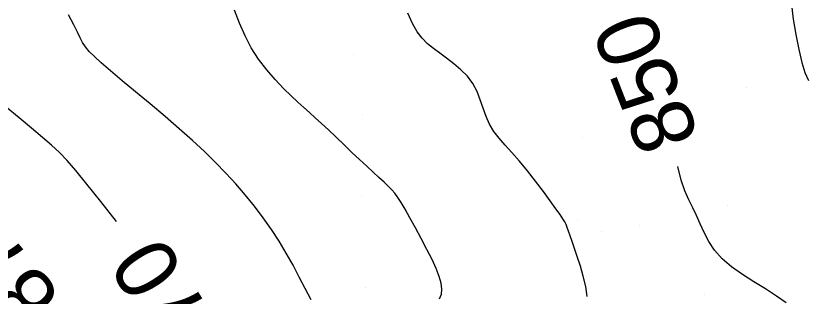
# Model space of a CAD drawing. Extents: x 400243 to 403697, y 4403637 to 4408083.
# Drawn here: x 402859.8 to 402954.4, y 4406058.5 to 4406092.2 of the extents above; entities that cross this region are included whole.
import ezdxf

# ---------------------------------------------------------------- set-up
doc = ezdxf.new("R2010")
doc.units = 0
doc.layers.add('HH_IC', color=7, linetype='Continuous')

msp = doc.modelspace()

# ---------------------------------------------------------------- linework, layer by layer
at = {"layer": 'HH_IC'}
for p, q in [((402929.135, 4406088.532), (402929.135, 4406088.532)), ((402900.255, 4406087.517), (402900.255, 4406087.517)), ((402937.596, 4406086.879), (402937.596, 4406086.879)), ((402947.338, 4406083.635), (402947.338, 4406083.635)), ((402901.353, 4406080.309), (402901.353, 4406080.309)), ((402927.759, 4406077.572), (402927.759, 4406077.572)), ((402901.274, 4406070.527), (402901.274, 4406070.527)), ((402945.109, 4406069.393), (402945.109, 4406069.393)), ((402927.092, 4406067.677), (402927.092, 4406067.677)), ((402934.544, 4406067.01), (402934.544, 4406067.01)), ((402930.017, 4406066.285), (402930.017, 4406066.285)), ((402901.728, 4406059.615), (402901.728, 4406059.615)), ((402942.308, 4406058.705), (402942.308, 4406058.705))]:
    msp.add_line(p, q, dxfattribs=at)
for points in [[(402954.84, 4406097.908), (402954.088, 4406097.631), (402953.486, 4406097.392), (402953.043, 4406097.106), (402952.751, 4406096.671), (402952.606, 4406095.987), (402952.601, 4406094.951), (402952.726, 4406093.507), (402952.955, 4406091.778), (402953.258, 4406089.935), (402953.604, 4406088.147), (402953.962, 4406086.583), (402954.323, 4406085.366), (402954.756, 4406084.423)], [(402910.57, 4406058.237), (402910.8, 4406058.77), (402910.873, 4406059.38), (402910.786, 4406060.088), (402910.551, 4406060.907), (402910.178, 4406061.852), (402909.678, 4406062.936), (402909.069, 4406064.159), (402908.393, 4406065.455), (402907.698, 4406066.743), (402907.033, 4406067.942), (402906.447, 4406068.972), (402905.972, 4406069.776), (402905.579, 4406070.392), (402905.223, 4406070.885), (402904.858, 4406071.316), (402904.439, 4406071.75), (402903.929, 4406072.239), (402903.325, 4406072.797), (402902.634, 4406073.428), (402901.86, 4406074.136), (402901.009, 4406074.925), (402900.091, 4406075.792), (402899.138, 4406076.703), (402898.186, 4406077.614), (402897.271, 4406078.484), (402896.43, 4406079.272), (402895.685, 4406079.951), (402895, 4406080.563), (402894.326, 4406081.165), (402893.614, 4406081.814), (402892.815, 4406082.569), (402891.898, 4406083.473), (402890.902, 4406084.522), (402889.886, 4406085.697), (402888.909, 4406086.979), (402888.028, 4406088.35), (402887.282, 4406089.794), (402886.631, 4406091.297), (402886.015, 4406092.848)], [(402871.885, 4406067.487), (402869.998, 4406069.914), (402868.342, 4406072.002), (402867.029, 4406073.607), (402865.975, 4406074.82), (402865.046, 4406075.789), (402864.11, 4406076.664), (402863.034, 4406077.595), (402861.723, 4406078.694), (402860.241, 4406079.924), (402858.691, 4406081.214), (402857.175, 4406082.491), (402855.797, 4406083.682), (402854.629, 4406084.737), (402853.629, 4406085.698), (402852.722, 4406086.633), (402851.838, 4406087.605), (402850.902, 4406088.682), (402849.853, 4406089.911), (402848.669, 4406091.272), (402847.34, 4406092.725)], [(402895.187, 4406058.096), (402894.496, 4406059.447), (402893.78, 4406060.843), (402893.027, 4406062.267), (402892.228, 4406063.704), (402891.37, 4406065.139), (402890.445, 4406066.559), (402889.456, 4406067.959), (402888.411, 4406069.336), (402887.315, 4406070.686), (402886.176, 4406072.007), (402884.995, 4406073.301), (402883.752, 4406074.586), (402882.423, 4406075.886), (402880.984, 4406077.226), (402879.41, 4406078.629), (402877.697, 4406080.105), (402875.92, 4406081.601), (402874.176, 4406083.055), (402872.56, 4406084.399), (402871.166, 4406085.57), (402870.068, 4406086.521), (402869.236, 4406087.286), (402868.62, 4406087.918), (402868.166, 4406088.47), (402867.822, 4406088.996), (402867.531, 4406089.554), (402867.21, 4406090.229), (402866.774, 4406091.111), (402866.134, 4406092.29)], [(402928.258, 4406058.507), (402928.091, 4406059.706), (402927.802, 4406060.946), (402927.447, 4406062.162), (402927.083, 4406063.287), (402926.757, 4406064.265), (402926.476, 4406065.095), (402926.236, 4406065.788), (402926.035, 4406066.352), (402925.869, 4406066.799), (402925.728, 4406067.15), (402925.572, 4406067.471), (402925.352, 4406067.84), (402925.02, 4406068.333), (402924.528, 4406069.029), (402923.846, 4406069.976), (402923.011, 4406071.113), (402922.08, 4406072.348), (402921.107, 4406073.592), (402920.148, 4406074.755), (402919.251, 4406075.77), (402918.433, 4406076.667), (402917.705, 4406077.497), (402917.078, 4406078.315), (402916.56, 4406079.173), (402916.151, 4406080.109), (402915.805, 4406081.102), (402915.463, 4406082.116), (402915.069, 4406083.114), (402914.564, 4406084.06), (402913.909, 4406084.926), (402913.136, 4406085.712), (402912.294, 4406086.428), (402911.432, 4406087.082), (402910.602, 4406087.682), (402909.841, 4406088.246), (402909.148, 4406088.826), (402908.509, 4406089.483), (402907.911, 4406090.277), (402907.341, 4406091.269), (402906.788, 4406092.5)], [(402952.093, 4406057.725), (402950.938, 4406058.564), (402949.626, 4406059.406), (402948.236, 4406060.26), (402946.851, 4406061.14), (402945.553, 4406062.059), (402944.425, 4406063.029), (402943.527, 4406064.056), (402942.826, 4406065.119), (402942.268, 4406066.188), (402941.796, 4406067.232), (402941.355, 4406068.224), (402940.901, 4406069.154), (402940.437, 4406070.104), (402939.976, 4406071.176), (402939.531, 4406072.473), (402939.117, 4406074.098)]]:
    msp.add_lwpolyline(points, dxfattribs=at)

# ---------------------------------------------------------------- texts
for s, rotation, p in [('850', 111.17377, (402941.775, 4406077.617)), ('875', 129.74423, (402865.43, 4406058.51)), ('870', 122.39643, (402886.109, 4406052.069))]:
    msp.add_text(s, height=7.5, rotation=rotation, dxfattribs=at).set_placement(p)

doc.saveas('drawing.dxf')
